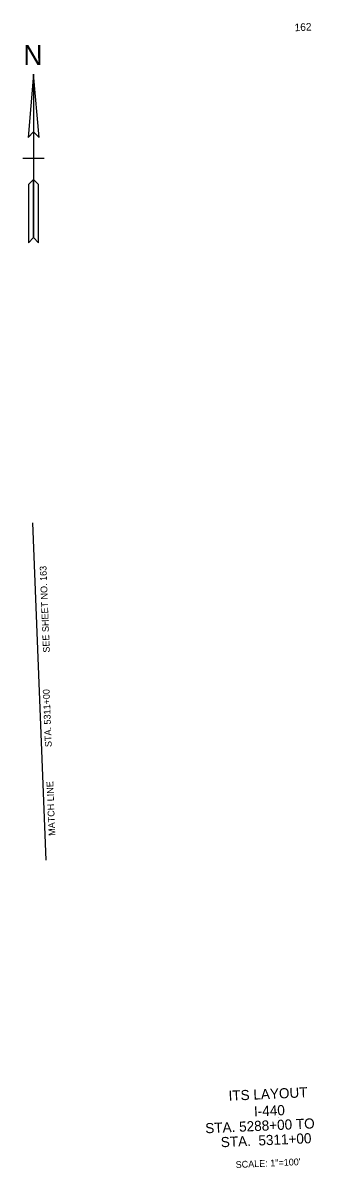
# Model space of a CAD drawing. Extents: x -200 to 1745707, y -325 to 653011.
# Drawn here: x 1745190 to 1745707, y 650975 to 653011 of the extents above; entities that cross this region are included whole.
import ezdxf

# ---------------------------------------------------------------- set-up
doc = ezdxf.new("R2010")
doc.units = 0
for name, color, linetype in [('DESIGN - CENTERLINE - Proposed Text', 7, 'Continuous'), ('DESIGN - SCRATCH - User 1', 7, 'Continuous'), ('DESIGN - SHEET - Corner Text', 7, 'Continuous'), ('ITS - CONST TEXT', 7, 'Continuous'), ('ITS - EXISITING WEATHER STATION', 7, 'Continuous'), ('ITS - EXISTING COMM CABLE', 7, 'Continuous'), ('ITS - EXISTING HAR', 7, 'Continuous')]:
    doc.layers.add(name, color=color, linetype=linetype)

msp = doc.modelspace()

# ---------------------------------------------------------------- linework, layer by layer
at = {"layer": 'DESIGN - CENTERLINE - Proposed Text'}
for p, q in [((1745208.6, 652769.8), (1745189.7, 652769.8)), ((1745227.5, 652769.8), (1745208.6, 652769.8))]:
    msp.add_line(p, q, dxfattribs=at)
msp.add_lwpolyline([(1745208.6, 652919.8), (1745198.8, 652807.2), (1745208.6, 652817), (1745218.4, 652807.2), (1745208.6, 652919.8), (1745208.6, 652628.9), (1745217.7, 652619.8), (1745217.7, 652723.3), (1745208.6, 652732.4), (1745199.5, 652723.3), (1745199.5, 652619.8), (1745208.6, 652628.9)], dxfattribs=at)
for points in [[(1745208.6, 652817), (1745218.4, 652807.2), (1745208.6, 652919.8)], [(1745199.5, 652619.8), (1745208.6, 652628.9), (1745208.6, 652732.4), (1745199.5, 652723.3)]]:
    msp.add_lwpolyline(points, close=True, dxfattribs=at)
at = {"layer": 'DESIGN - SCRATCH - User 1'}
for p, q in [((1745643.9, 651064.3), (1745643.9, 651064.3)), ((1745643.9, 651064.3), (1745643.9, 651064.3)), ((1745647.9, 651048.1), (1745647.9, 651048.1))]:
    msp.add_line(p, q, dxfattribs=at)
at = {"layer": 'ITS - EXISITING WEATHER STATION'}
msp.add_line((1745643.8, 651064.4), (1745643.8, 651064.4), dxfattribs=at)
msp.add_line((1745643.8, 651064.4), (1745643.8, 651064.4), dxfattribs=at)
at = {"layer": 'ITS - EXISTING COMM CABLE'}
msp.add_line((1745231.1, 651522.4), (1745207.2, 652121.9), dxfattribs=at)

# ---------------------------------------------------------------- texts
at = {"layer": 'DESIGN - CENTERLINE - Proposed Text'}
msp.add_text('N', height=35.4, dxfattribs=at).set_placement((1745190.5, 652935.9))
at = {"layer": 'DESIGN - SHEET - Corner Text'}
msp.add_text('162', height=13.5, rotation=2.6113, dxfattribs=at).set_placement((1745673.1, 652995.8))
at = {"layer": 'ITS - CONST TEXT'}
msp.add_text('SCALE: 1"=100\'', height=12, rotation=2.6113, dxfattribs=at).set_placement((1745568.3, 650974.8))
at = {"layer": 'ITS - EXISTING COMM CABLE'}
for s, p in [('SEE SHEET NO. 163 ', (1745237.6, 651891.4)), ('STA. 5311+00', (1745241.1, 651723.5)), ('MATCH LINE', (1745247.4, 651565.6))]:
    msp.add_text(s, height=12, rotation=92.2768, dxfattribs=at).set_placement(p)
at = {"layer": 'ITS - EXISTING HAR'}
for s, p in [('ITS LAYOUT', (1745555.8, 651094.3)), ('I-440', (1745601, 651066.5)), ('STA. 5288+00 TO', (1745514.4, 651036.5)), ('STA.  5311+00', (1745542, 651011.7))]:
    msp.add_text(s, height=18, rotation=2.6113, dxfattribs=at).set_placement(p)

doc.saveas('drawing.dxf')
